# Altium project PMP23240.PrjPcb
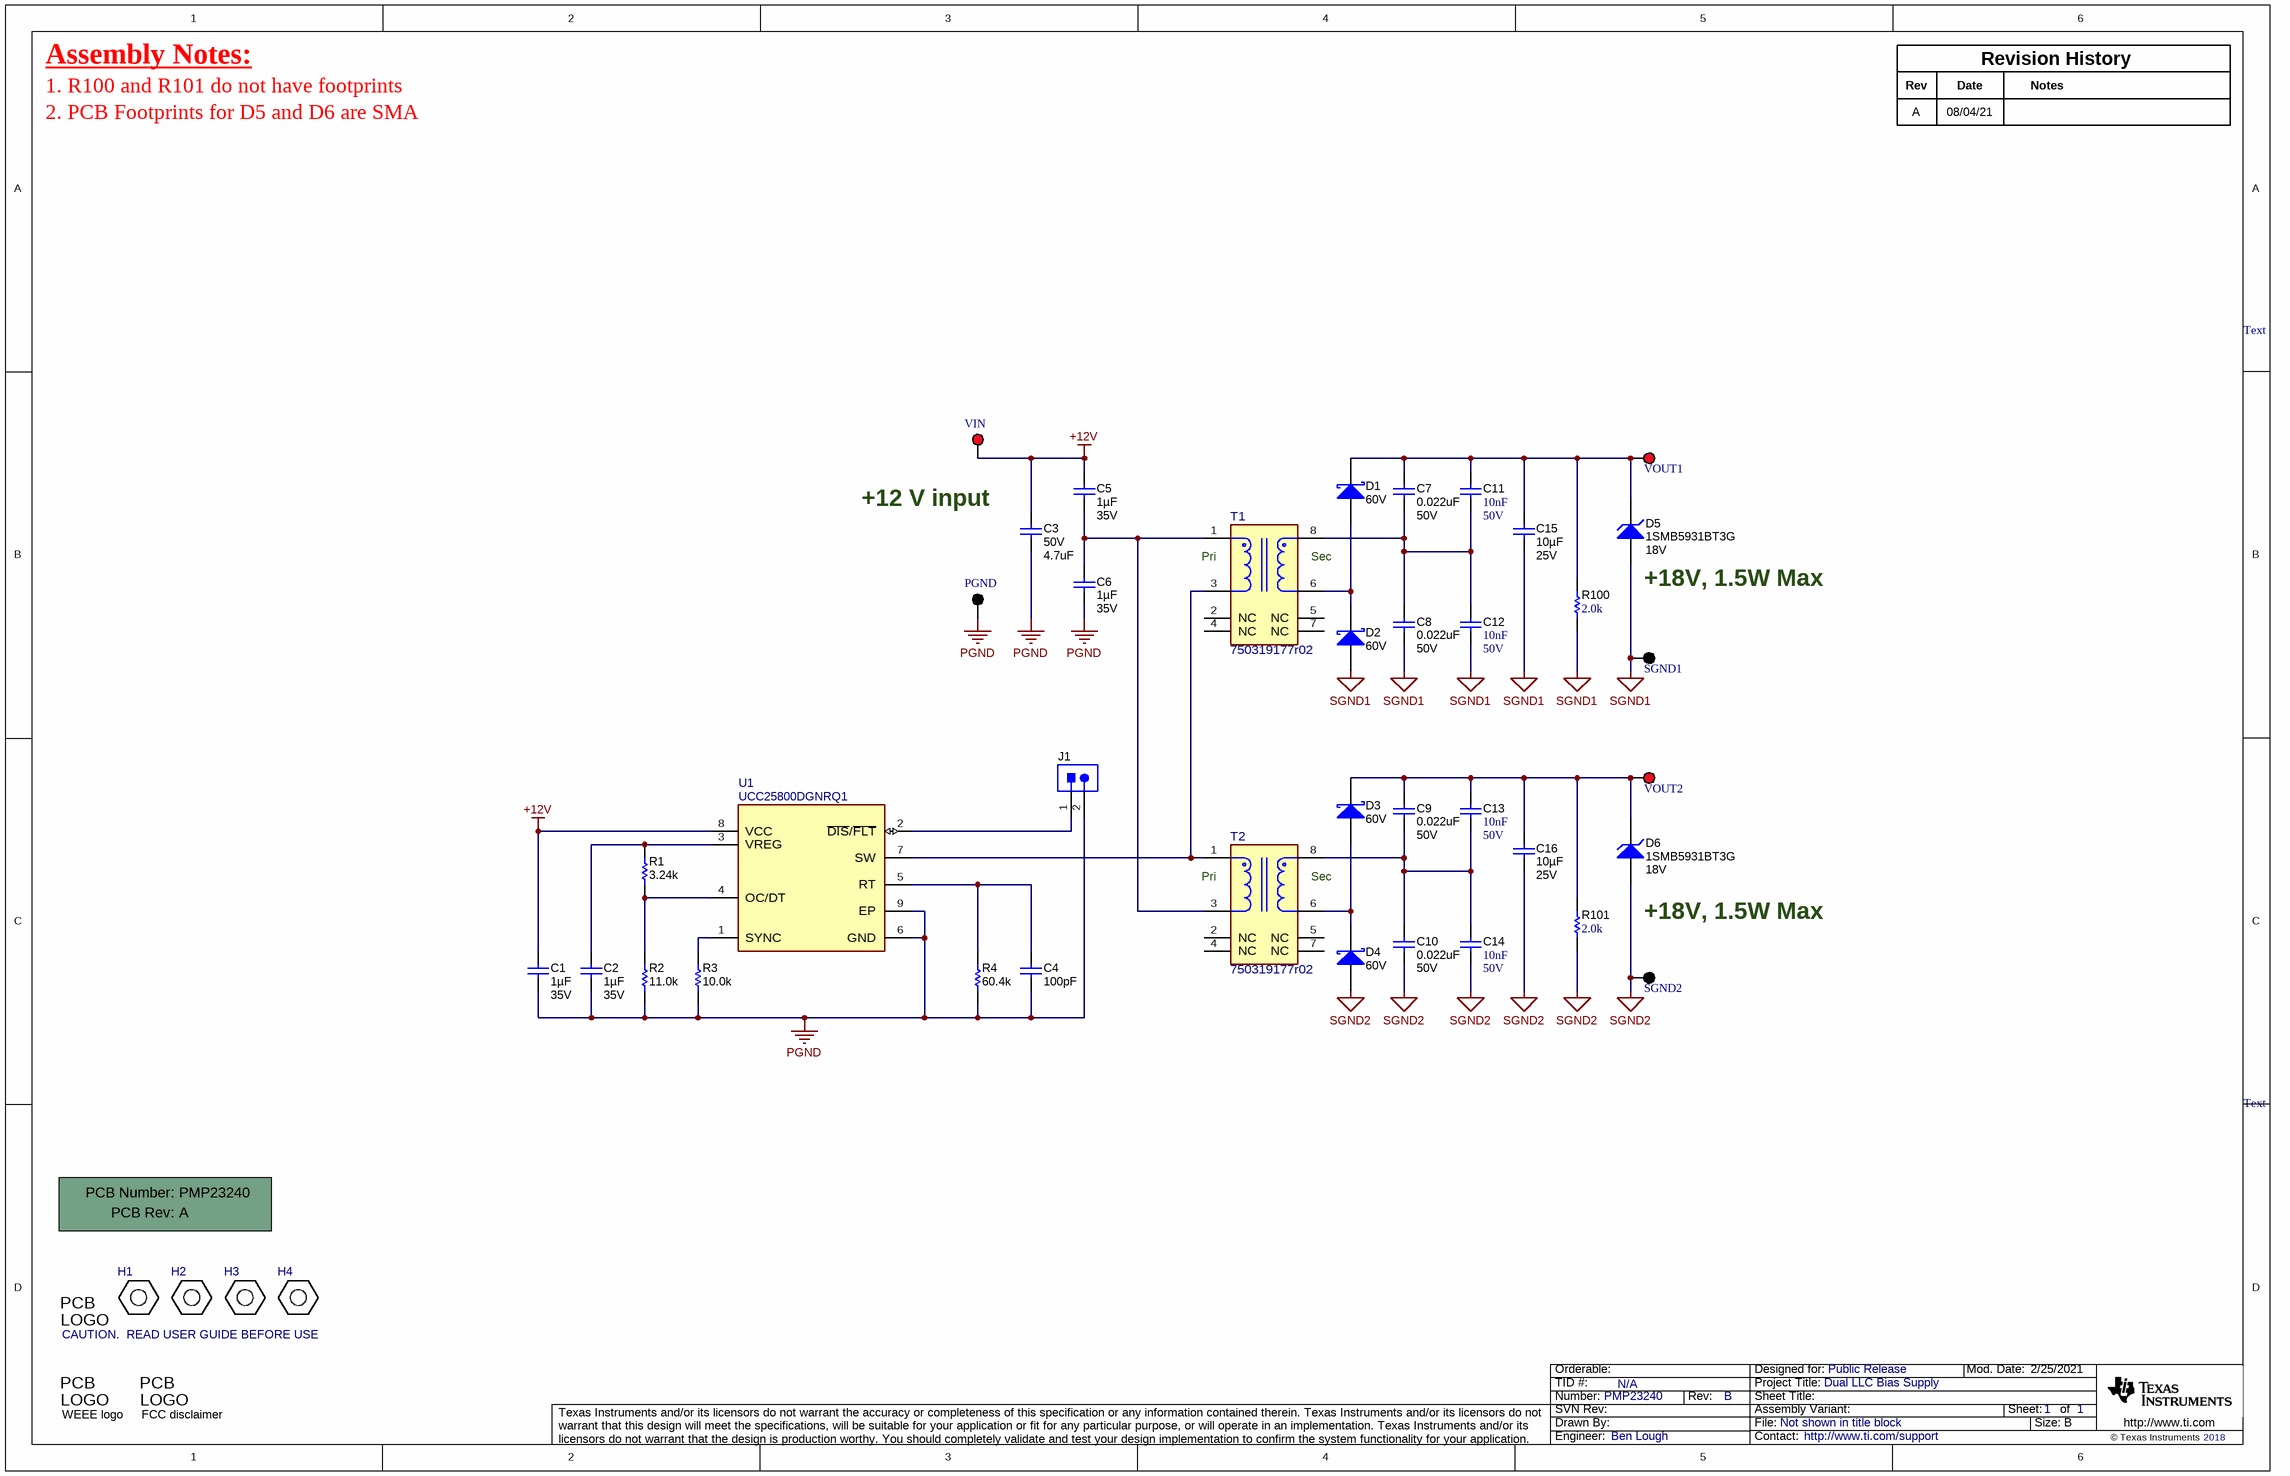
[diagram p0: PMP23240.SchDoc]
TID: N/A; TechSupport: http://www.ti.com/support; SCH_Rev: B; PRJ_Title: Dual LLC Bias Supply; PRJ_Number: PMP23240; PRJ_Engineer: Ben Lough; PRJ_Customer: Public Release; PCB_Rev: A; PCB_Layout: Ben Lough; CopyrightYear: 2018
1 sheet, 46 parts. Net scope: global (net labels, ports and power ports of the same name join across sheets).
Board file: PMP23240.PcbDoc

## Sheet PMP23240.SchDoc
size 431 x 279 mm; Date: Not shown in title block; ApprovedBy: Not shown in title block; CheckedBy: Not shown in title block; Author: Not shown in title block; CompanyName: Not shown in title block; Engineer: Not shown in title block; Organization: Not shown in title block; Address1: Not shown in title block; Address2: Not shown in title block; Address3: Not shown in title block; Address4: Not shown in title block; DocumentNumber: 1; Revision: Use project parameter SCH_Rev; SheetNumber: 1; SheetTotal: 1; PageSetup: Record=PageOptions¦CenterHorizontal=True¦CenterVertical=True¦PrintScale=1.00¦XCorrection=1.00¦YCorrection=1.00¦PrintKind=0¦BorderSize=5000000¦LeftOffset=0¦BottomOffset=0¦Orientation=2¦PaperLength=1000¦PaperWidth=1000¦Scale=100¦PaperSource=15¦PrintQuality=600¦MediaType=1¦DitherType=10¦PaperKind=Letter¦PrintScaleMode=1

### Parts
!PCB1  Printed Circuit Board  (value not drawn)  (mechanical)
C1  Cap_F: 1µF  VDC_V: 35V  [0805_HV]  (hidden comment: GRM219R7YA105KA12D)
C2  Cap_F: 1µF  VDC_V: 35V  [0805_HV]  (hidden comment: GRM219R7YA105KA12D)
C3  VDC_V: 50V  ValueDisplayed: 4.7uF  [1206_180]  (hidden comment: GRM31CR71H475KA12L)
C4  ValueDisplayed: 100pF  [0603]  (hidden comment: GRM1885C1H101JA01D)
C5  Cap_F: 1µF  VDC_V: 35V  [0805_HV]  (hidden comment: GRM219R7YA105KA12D)
C6  Cap_F: 1µF  VDC_V: 35V  [0805_HV]  (hidden comment: GRM219R7YA105KA12D)
C7  value 0.022uF  VDC_V: 50V  [0603]  (hidden comment: GRM188R71H223KA01D)
C8  value 0.022uF  VDC_V: 50V  [0603]  (hidden comment: GRM188R71H223KA01D)
C9  value 0.022uF  VDC_V: 50V  [0603]  (hidden comment: GRM188R71H223KA01D)
C10  value 0.022uF  VDC_V: 50V  [0603]  (hidden comment: GRM188R71H223KA01D)
C11  Cap_F: 10nF  VDC_V: 50V  [0603]  (hidden comment: GRM188R71H103KA01D)
C12  Cap_F: 10nF  VDC_V: 50V  [0603]  (hidden comment: GRM188R71H103KA01D)
C13  Cap_F: 10nF  VDC_V: 50V  [0603]  (hidden comment: GRM188R71H103KA01D)
C14  Cap_F: 10nF  VDC_V: 50V  [0603]  (hidden comment: GRM188R71H103KA01D)
C15  Cap_F: 10µF  VDC_V: 25V  [0805L]  (hidden comment: GRM21BZ71E106KE15L)
C16  Cap_F: 10µF  VDC_V: 25V  [0805L]  (hidden comment: GRM21BZ71E106KE15L)
D1  Vr_V: 60V  [SOD-123]  (hidden comment: PMEG6010CEGWJ)
D2  Vr_V: 60V  [SOD-123]  (hidden comment: PMEG6010CEGWJ)
D3  Vr_V: 60V  [SOD-123]  (hidden comment: PMEG6010CEGWJ)
D4  Vr_V: 60V  [SOD-123]  (hidden comment: PMEG6010CEGWJ)
D5  1SMB5931BT3G  value 18V  [SMB]
D6  1SMB5931BT3G  value 18V  [SMB]
H1  4824  [KEYSTONE_4824]  (value not drawn)
H2  4824  [KEYSTONE_4824]  (value not drawn)
H3  4824  [KEYSTONE_4824]  (value not drawn)
H4  4824  [KEYSTONE_4824]  (value not drawn)
J1  22284023  [Molex_0022284023]  (value not drawn)
Logo1  CAUTION.  READ USER GUIDE BEFORE USE  [IEC_Caution_Small]  (no BOM)
Logo2  WEEE logo  [WEEE_Minimum]  (no BOM)
Logo3  FCC disclaimer  [FCC_disclaimer]  (no BOM)
PGND  5011  [Keystone5011]  (value not drawn)
R1  ValueDisplayed: 3.24k  [0603]  (hidden comment: CRCW06033K24FKEA)
R2  ValueDisplayed: 11.0k  [0603]  (hidden comment: CRCW060311K0FKEA)
R3  ValueDisplayed: 10.0k  [0603]  (hidden comment: CRCW060310K0FKEA)
R4  ValueDisplayed: 60.4k  [0603]  (hidden comment: CRCW060360K4FKEA)
R100  ValueDisplayed: 2.0k  [1206]  (hidden comment: CRCW12062K00JNEA)
R101  ValueDisplayed: 2.0k  [1206]  (hidden comment: CRCW12062K00JNEA)
SGND1  5011  [Keystone5011]  (value not drawn)
SGND2  5011  [Keystone5011]  (value not drawn)
T1  750319177r02  [FP-750319177r02_SMT_11MM21_11MM3-MFG]
T2  750319177r02  [FP-750319177r02_SMT_11MM21_11MM3-MFG]
U1  UCC25800DGNRQ1  [DGN0008G-MFG]
VIN  5010  [Keystone5010]  (value not drawn)
VOUT1  5010  [Keystone5010]  (value not drawn)
VOUT2  5010  [Keystone5010]  (value not drawn)

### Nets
+12V: C1.1 C3.1 C5.1 U1.8(VCC) VIN.1
PGND: C1.2 C2.2 C3.2 C4.2 C6.2 J1.2 PGND.1 R2.1 R3.1 R4.1 U1.6(GND) U1.9(EP)
SGND1: C8.1 C12.2 C15.2 D2.2(A) D5.2(A) R100.1 SGND1.1
SGND2: C10.1 C14.2 C16.2 D4.2(A) D6.2(A) R101.1 SGND2.1
NetC2_1: C2.1 R1.2 U1.3(VREG)
NetC4_1: C4.1 R4.2 U1.5(RT)
NetC5_2: C5.2 C6.1 T1.1 T2.3
NetC7_1: C7.1 C8.2 C11.2 C12.1 T1.8
NetC7_2: C7.2 C11.1 C15.1 D1.1(K) D5.1(K) R100.2 VOUT1.1
NetC9_1: C9.1 C10.2 C13.2 C14.1 T2.8
NetC9_2: C9.2 C13.1 C16.1 D3.1(K) D6.1(K) R101.2 VOUT2.1
NetD1_2: D1.2(A) D2.1(K) T1.6
NetD3_2: D3.2(A) D4.1(K) T2.6
NetJ1_1: J1.1 U1.2(~{DIS}/~{FLT})
NetR1_1: R1.1 R2.2 U1.4(OC/DT)
NetR3_2: R3.2 U1.1(SYNC)
NetT1_3: T1.3 T2.1 U1.7(SW)

Not connected (* = marked no-connect by the designer): T1 2(NC) 4(NC) 5(NC) 7(NC); T2 2(NC) 4(NC) 5(NC) 7(NC)

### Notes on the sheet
- Assembly Notes:
- 1. R100 and R101 do not have footprints
- Rev
- Date
- Notes
- Revision History
- 2. PCB Footprints for D5 and D6 are SMA
- A
- 08/04/21
- Text
- +12 V input
- (near T1) Pri
- (near T1) Sec
- (near D5) +18V, 1.5W Max
- (near T2) Pri
- (near T2) Sec
- +18V, 1.5W Max

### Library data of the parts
!PCB1 = CMP-0003618-2: Manufacturer: Any; PartNumber: PMP23240
C1 C2 C5 C6 = CMP-0085980-1: CAP, CERM, 1 µF, 35 V,+/- 10%, X7R, 0805; Manufacturer: MuRata; AEC Category: Q200; SizeZ_mm: 1.45; U/M: EA; Cap_Case: 0805; Polarized: N; Value: 1uF; TaMin_C: -55°C; TaMax_C: 125°C; SizeArea_mm2: 2.5; SizeX_mm: 2; SizeY_mm: 1.25; SizeAreaWB_mm2: 6.75
C3 = CMP-0008969-2: CAP, CERM, 4.7 uF, 50 V, +/- 10%, X7R, 1206; Manufacturer: MuRata; TaMin_C: -55°C; Polarized: N; SizeAreaWB_mm2: 10.92; Value1: Unknown; U/M: EA; Value: 4.7uF; TaMax_C: 125°C; SizeZ_mm: 1.8; SizeX_mm: 3.2; SizeY_mm: 1.6; Cap_Case: 2220; SizeArea_mm2: 5.12; Cap_F: 4.7µF; AEC Category: Q200
C4 = CMP-0007171-4: CAP, CERM, 100 pF, 50 V, +/- 5%, C0G/NP0, 0603; Manufacturer: MuRata; TaMin_C: -55°C; Polarized: N; SizeAreaWB_mm2: 4.68; Value1: Unknown; U/M: EA; Value: 100pF; TaMax_C: 125°C; SizeZ_mm: 1; SizeX_mm: 1.6; SizeY_mm: 0.8; Value2: 50V; SizeArea_mm2: 1.28; AEC Category: Q200
C7-C10 = CMP-0007444-5: CAP, CERM, 0.022 uF, 50 V, +/- 10%, X7R, 0603; Manufacturer: MuRata; U/M: EA; SizeX_mm: 1.6; Polarized: N; TaMin_C: -55°C; Cap_F: 22nF; SizeZ_mm: 1; AEC Category: Q200; SizeAreaWB_mm2: 4.68; SizeY_mm: 0.8; TaMax_C: 125°C; SizeArea_mm2: 1.28; MFG_Status: TI_Obsolete; Value1: Unknown
C11-C14 = CMP-0007433-4: CAP, CERM, 0.01 uF, 50 V, +/- 10%, X7R, 0603; Manufacturer: MuRata; TaMin_C: -55°C; Polarized: N; SizeAreaWB_mm2: 4.68; Value1: Unknown; U/M: EA; Value: 0.01uF; TaMax_C: 125°C; SizeZ_mm: 1; SizeX_mm: 1.6; SizeY_mm: 0.8; SizeArea_mm2: 1.28; AEC Category: Q200
C15 C16 = CMP-0008378-2: CAP, CERM, 10 uF, 25 V, +/- 10%, X7R, 0805; Manufacturer: MuRata; TaMin_C: -55°C; Polarized: N; SizeAreaWB_mm2: 6.75; Value1: Unknown; U/M: EA; Value: 10uF; TaMax_C: 125°C; SizeZ_mm: 1.45; SizeX_mm: 2; SizeY_mm: 1.25; Cap_Case: 0805; SizeArea_mm2: 2.5; AEC Category: Q200
D1-D4 = CMP-0079239-2: Diode, Schottky, 60 V, 1 A, AEC-Q101, SOD-123; Manufacturer: Nexperia; SizeY_mm: 1.7; AEC Qualified: Y; SizeArea_mm2: 6.545; Vf_V: 660mV; Value: 60V; Value1: 1A; AEC Category: Q101; TJmax_C: 150°C; SizeX_mm: 3.85; SizeZ_mm: 1.35; SizeAreaWB_mm2: 13.095; Value2: 0.66V
D5 D6 = CMP-0005632-4: Diode, Zener, 18 V, 550 mW, SMB; Manufacturer: ON Semiconductor; SizeX_mm: 5.6; SizeZ_mm: 2.6; Power_W: 550mW; Value1: 0.55W; SizeArea_mm2: 21.336; SizeY_mm: 3.81; AEC Category: Q101; RJA_CperW: 226; SizeAreaWB_mm2: 44.156
H1-H4 = CMP-0003690-1: Manufacturer: Keystone; CompType: Standoff
J1 = CMP-0055333-1: Header, 2.54mm, 2x1, Tin, TH; Manufacturer: Molex; CNHeader: TRUE; Current_A: 4A; Shrouded: N; Gender: Male; Voltage_V: 250V; Row_Count: 1; Pitch_mm: 2.54; CT: FALSE; Cert_UL: Y
Logo1 = CMP-0074836-1: IEC 61010-1 Caution Warning; SymbolCreator: a0412235; Lib Reference: IEC_Caution
Logo2 = CMP-0074769-1
Logo3 = CMP-0074847-1: FCC_disclaimer; Library Reference: Logo
PGND SGND1 SGND2 = CMP-0055148-1: Test Point, Multipurpose, Black, TH; Manufacturer: Keystone; CNHeader: FALSE; Green_Lifecycle: Active; Green_REACh: Passed; ContactFinish: Silver; CT: TRUE
R1 = CMP-0022374-4: RES, 3.24 k, 1%, 0.1 W, AEC-Q200 Grade 0, 0603; Manufacturer: Vishay-Dale; Power_W: 100mW; TempCo: 100 ppm/C; Value_Code: 3k24; Value: 3.24k; EIA_Code: E96; SizeX_mm: 1.6; SizeY_mm: 0.8; SizeZ_mm: 1; Value2: 0.1W; SizeArea_mm2: 1.28; AEC Qualified: Y; VDC_V: 75V; AEC Category: Q200; AEC Grade: 0
R2 = CMP-0022016-4: RES, 11.0 k, 1%, 0.1 W, AEC-Q200 Grade 0, 0603; Manufacturer: Vishay-Dale; Power_W: 100mW; TempCo: 100 ppm/C; Value_Code: 11k0; Value: 11.0k; EIA_Code: E96; Res_ohm: 11k; SizeX_mm: 1.6; SizeY_mm: 0.8; SizeZ_mm: 1; Value2: 0.1W; SizeArea_mm2: 1.28; AEC Qualified: Y; VDC_V: 75V; AEC Category: Q200; AEC Grade: 0
R3 = CMP-0021998-4: RES, 10.0 k, 1%, 0.1 W, AEC-Q200 Grade 0, 0603; Manufacturer: Vishay-Dale; Power_W: 100mW; TempCo: 100 ppm/C; Value_Code: 10k0; Value: 10.0k; EIA_Code: E96; Res_ohm: 10k; SizeX_mm: 1.6; SizeY_mm: 0.8; SizeZ_mm: 1; Value2: 0.1W; SizeArea_mm2: 1.28; AEC Qualified: Y; VDC_V: 75V; AEC Category: Q200; AEC Grade: 0
R4 = CMP-0022532-4: RES, 60.4 k, 1%, 0.1 W, AEC-Q200 Grade 0, 0603; Manufacturer: Vishay-Dale; Power_W: 100mW; TempCo: 100 ppm/C; Value_Code: 60k4; Value: 60.4k; EIA_Code: E96; SizeX_mm: 1.6; SizeY_mm: 0.8; SizeZ_mm: 1; Value2: 0.1W; SizeArea_mm2: 1.28; AEC Qualified: Y; VDC_V: 75V; AEC Category: Q200; AEC Grade: 0
R100 R101 = CMP-0018640-3: RES, 2.0 k, 5%, 0.25 W, AEC-Q200 Grade 0, 1206; Manufacturer: Vishay-Dale; Power_W: 250mW; TempCo: 200 ppm/C; Value_Code: 2k00; Value: 2.0k; EIA_Code: E24; Res_ohm: 2k; SizeX_mm: 3.2; SizeY_mm: 1.6; SizeZ_mm: 1.35; Value2: 0.25W; SizeArea_mm2: 5.12; AEC Qualified: Y; VDC_V: 200V; AEC Category: Q200; AEC Grade: 0
T1 T2 = CMP-0091345-1: Transformer, 1:1.67, 0.045Ohm Pri, 0.122Ohm Sec, 16.5uH; Manufacturer: Wurth Electronics; AEC Qualified: No; Rsec1_ohm: 0.122; Ind_H: 16.5µH; Frequency_Fixed: 500kHz; SizeZ_mm: 12.2mm; DCR_ohm: 45m
U1 = CMP-0088494-2: Open Loop LLC Transformer Driver for Isolated Bias Supplies; Manufacturer: Texas Instruments; Min Supply Voltage: 12V; SizeZ_mm: 1.1mm; Number Of Outputs: 1; Standoff Height: 0.05mm; AEC Category: Q200; Max Duty Cycle: 50%; TaMin_C: -40°C; TJmax_C: +150°C; AEC Qualified: No; Switching Frequency: 100-2000kHz; CompType: IC; Max Supply Voltage: 36V; TaMax_C: +125°C; Output Type: Other; Nominal Supply Current: 500uA
VIN VOUT1 VOUT2 = CMP-0055147-1: Test Point, Multipurpose, Red, TH; Manufacturer: Keystone; CNHeader: FALSE; Green_Lifecycle: Active; Green_REACh: Passed; ContactFinish: Silver; CT: TRUE

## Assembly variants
001: not fitted H1 H2 H3 H4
